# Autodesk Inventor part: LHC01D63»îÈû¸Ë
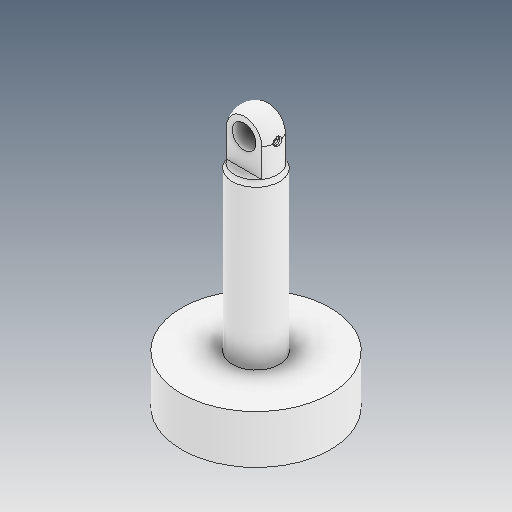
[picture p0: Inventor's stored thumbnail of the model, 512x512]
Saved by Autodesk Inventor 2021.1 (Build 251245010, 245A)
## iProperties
Created: 2021-06
Part Number: LHC01D63»îÈû¸Ë
Material: Ogólny
Document SubType Name: Modeling
Designer: user
Density: 1 g/cm^3
Appearance: Domyślna
Author: user
Revision Number: ÈÎºÎ
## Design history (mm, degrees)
feature "ÊäÈë1"
node "Bryła1"
